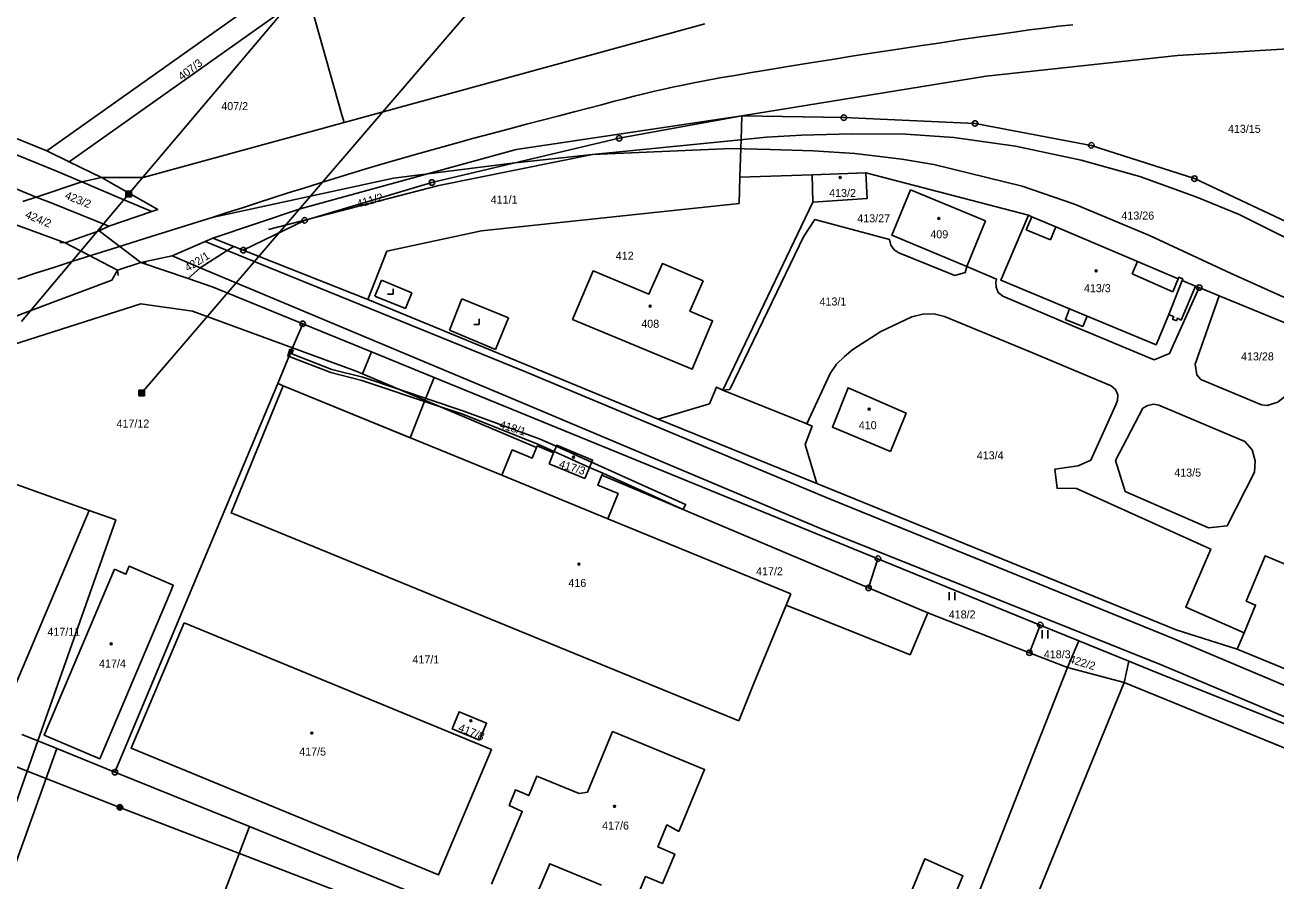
# Model space of a CAD drawing. Extents: x -587171 to -555306, y -1167727 to -1074732.
# Drawn here: x -560606.6 to -560378.5, y -1078590.7 to -1078434.4 of the extents above; entities that cross this region are included whole.
import ezdxf

# ---------------------------------------------------------------- set-up
doc = ezdxf.new("R2010")
doc.units = 0
for name, color, linetype in [('Hranice parcel', 7, 'Continuous'), ('Parcelní čísla', 7, 'Continuous'), ('Poz předměty', 7, 'Continuous'), ('Vnitřní kresba', 7, 'Continuous'), ('Věcná břemena k části', 7, 'Continuous'), ('Značky bodu BP', 7, 'Continuous'), ('Značky budov', 7, 'Continuous'), ('Značky kultur', 7, 'Continuous')]:
    doc.layers.add(name, color=color, linetype=linetype)

msp = doc.modelspace()

# ---------------------------------------------------------------- linework, layer by layer
at = {"layer": 'Hranice parcel'}
for p, q in [((-560602.65, -1078457.42), (-560556.22, -1078424.49)), ((-560555.07, -1078428.57), (-560598.55, -1078459.41)), ((-560342.84, -1078436.82), (-560396.43, -1078439.99)), ((-560640.02, -1078442.1), (-560602.65, -1078457.42)), ((-560640.44, -1078451.19), (-560604.57, -1078465.85)), ((-560585.07, -1078462.27), (-560548.39, -1078452.22)), ((-560602.65, -1078457.42), (-560598.55, -1078459.41)), ((-560598.55, -1078459.41), (-560592.63, -1078462.29)), ((-560592.63, -1078462.29), (-560585.07, -1078462.27)), ((-560463.06, -1078461.81), (-560476.23, -1078462.2)), ((-560453.25, -1078461.44), (-560463.06, -1078461.81)), ((-560462.92, -1078466.77), (-560463.06, -1078461.81)), ((-560453.25, -1078461.44), (-560423.57, -1078469.17)), ((-560604.57, -1078465.85), (-560606.99, -1078466.66)), ((-560604.57, -1078465.85), (-560601.84, -1078466.88)), ((-560601.84, -1078466.88), (-560591.3, -1078471.17)), ((-560479.35, -1078501.1), (-560462.92, -1078466.77)), ((-560572.37, -1078473.32), (-560568.53, -1078474.84)), ((-560568.53, -1078474.84), (-560566.79, -1078475.53)), ((-560566.79, -1078475.53), (-560544.07, -1078484.52)), ((-560585.48, -1078477.81), (-560576.86, -1078480.73)), ((-560393.13, -1078482.08), (-560392.45, -1078482.36)), ((-560388.8, -1078483.87), (-560392.45, -1078482.36)), ((-560544.07, -1078484.52), (-560491.12, -1078506.35)), ((-560388.8, -1078483.87), (-560371.78, -1078490.9)), ((-560555.96, -1078488.96), (-560557.8, -1078493.38)), ((-560557.8, -1078493.38), (-560546.21, -1078497.63)), ((-560546.21, -1078497.63), (-560513.3, -1078511.55)), ((-560451.04, -1078531.84), (-560532.01, -1078498.75)), ((-560519.65, -1078516.62), (-560559.52, -1078500.28)), ((-560491.12, -1078506.35), (-560462.21, -1078518.1)), ((-560500.32, -1078524.54), (-560519.65, -1078516.62)), ((-560452.76, -1078537.17), (-560501.4, -1078516.58)), ((-560611.42, -1078562.04), (-560594.92, -1078523.02)), ((-560466.92, -1078538.23), (-560500.32, -1078524.54)), ((-560452.76, -1078537.17), (-560451.04, -1078531.84)), ((-560421.44, -1078543.94), (-560451.04, -1078531.84)), ((-560441.97, -1078541.72), (-560452.76, -1078537.17)), ((-560467.8, -1078540.32), (-560466.92, -1078538.23)), ((-560441.97, -1078541.72), (-560423.42, -1078549)), ((-560423.42, -1078549), (-560421.44, -1078543.94)), ((-560414.4, -1078546.81), (-560421.44, -1078543.94)), ((-560416.49, -1078551.7), (-560414.4, -1078546.81)), ((-560405.27, -1078550.54), (-560414.4, -1078546.81)), ((-560385.52, -1078548.35), (-560384.25, -1078545.35)), ((-560423.42, -1078549), (-560416.49, -1078551.7)), ((-560385.52, -1078548.35), (-560330.86, -1078570.95)), ((-560446.84, -1078628.92), (-560416.49, -1078551.7)), ((-560406.12, -1078554.4), (-560416.49, -1078551.7)), ((-560406.12, -1078554.4), (-560405.27, -1078550.54)), ((-560318.62, -1078590.37), (-560406.12, -1078554.4)), ((-560604.25, -1078565.1), (-560609.07, -1078578.79)), ((-560604.25, -1078565.1), (-560607.16, -1078563.92)), ((-560600.81, -1078566.5), (-560604.25, -1078565.1)), ((-560638.59, -1078671.27), (-560600.81, -1078566.5)), ((-560590.21, -1078570.8), (-560600.81, -1078566.5)), ((-560590.21, -1078570.8), (-560565.69, -1078580.73)), ((-560604.5, -1078683.21), (-560565.69, -1078580.73)), ((-560565.69, -1078580.73), (-560446.84, -1078628.92))]:
    msp.add_line(p, q, dxfattribs=at)
for points in [[(-560555.07, -1078428.57), (-560548.79, -1078450.81), (-560548.39, -1078452.22)], [(-560548.39, -1078452.22), (-560484.63, -1078434.75), (-560482.64, -1078434.21)], [(-560396.43, -1078439.99), (-560431.28, -1078443.77), (-560475.85, -1078451.01)], [(-560475.85, -1078451.01), (-560517.03, -1078457.13), (-560556.44, -1078467.98), (-560572.37, -1078473.32)], [(-560475.85, -1078451.01), (-560498.24, -1078455.12), (-560532.39, -1078463.18), (-560555.6, -1078470.09), (-560566.79, -1078475.53)], [(-560476.23, -1078462.2), (-560476.05, -1078456.93), (-560476, -1078455.37), (-560475.85, -1078451.01)], [(-560475.85, -1078451.01), (-560457.27, -1078451.34), (-560433.34, -1078452.41), (-560412.13, -1078456.41), (-560393.32, -1078462.47), (-560368.14, -1078474.31), (-560366.28, -1078475.31)], [(-560592.63, -1078462.29), (-560596.23, -1078463.07), (-560604.57, -1078465.85)], [(-560592.63, -1078462.29), (-560582.38, -1078468.1), (-560583.46, -1078468.47), (-560591.3, -1078471.17)], [(-560544.07, -1078484.52), (-560540.61, -1078475.71), (-560523.37, -1078471.98), (-560476.37, -1078466.99), (-560476.23, -1078462.2)], [(-560462.92, -1078466.77), (-560453.04, -1078466.12), (-560453.25, -1078461.44)], [(-560431.45, -1078470.2), (-560445.1, -1078464.55), (-560448.53, -1078472.8), (-560434.85, -1078478.5), (-560431.45, -1078470.2)], [(-560591.3, -1078471.17), (-560593.05, -1078472.03), (-560599.28, -1078474.2), (-560613.44, -1078469.05)], [(-560423.57, -1078469.17), (-560428.66, -1078481), (-560416.09, -1078486.26), (-560416.86, -1078488.16), (-560413.65, -1078489.46), (-560412.87, -1078487.59), (-560400.33, -1078492.82), (-560398.02, -1078487.25), (-560397.11, -1078487.67), (-560397.3, -1078488.14), (-560396.62, -1078488.42), (-560396.43, -1078487.96), (-560395.77, -1078488.29), (-560393.13, -1078482.08)], [(-560393.13, -1078482.08), (-560395.57, -1078481.06), (-560395.46, -1078480.79), (-560396.15, -1078480.48), (-560396.27, -1078480.76), (-560403.72, -1078477.6), (-560418.59, -1078471.29), (-560422.96, -1078469.43), (-560423.57, -1078469.17)], [(-560392.45, -1078482.36), (-560397.87, -1078494.41), (-560400.64, -1078495.56), (-560415.67, -1078489.25), (-560428.26, -1078483.92), (-560429.11, -1078483.28), (-560429.48, -1078482.31), (-560429.55, -1078481.29), (-560429.44, -1078480.82), (-560434.85, -1078478.5), (-560435.12, -1078479.61), (-560437.02, -1078480.17), (-560447.22, -1078476), (-560448.11, -1078475.47), (-560448.71, -1078474.62), (-560448.96, -1078473.56), (-560462.55, -1078469.92), (-560464.62, -1078473.11), (-560471.14, -1078486.59), (-560478.07, -1078500.96), (-560479.35, -1078501.1)], [(-560585.48, -1078477.81), (-560579.74, -1078476.59), (-560573.74, -1078473.93), (-560572.37, -1078473.32)], [(-560576.86, -1078480.73), (-560574.63, -1078478.74), (-560569.71, -1078475.57), (-560568.53, -1078474.84)], [(-560647.85, -1078502.5), (-560647.06, -1078502.19), (-560644.13, -1078501.04), (-560642.96, -1078500.58), (-560590.78, -1078481.03), (-560589.74, -1078479.18), (-560585.48, -1078477.81)], [(-560482.94, -1078481.1), (-560490.33, -1078477.94), (-560492.81, -1078483.57), (-560502.99, -1078479.31), (-560506.74, -1078488.18), (-560484.92, -1078497.27), (-560481.21, -1078488.42), (-560485.36, -1078486.69), (-560482.94, -1078481.1)], [(-560576.86, -1078480.73), (-560572.28, -1078482.29), (-560555.96, -1078488.96)], [(-560371.78, -1078490.9), (-560372, -1078491.42), (-560376.52, -1078501.99), (-560378.14, -1078503.3), (-560380.08, -1078503.89), (-560381.11, -1078503.77), (-560392.16, -1078499.12), (-560392.91, -1078498.3), (-560393.21, -1078496.31), (-560388.8, -1078483.87)], [(-560462.21, -1078518.1), (-560464.32, -1078511.01), (-560463.05, -1078507.64), (-560464.03, -1078507.25), (-560459.73, -1078498.03), (-560458.59, -1078496.34), (-560457.16, -1078494.91), (-560455.6, -1078493.68), (-560450.54, -1078490.4), (-560444.84, -1078487.71), (-560442.88, -1078487.19), (-560440.87, -1078487.16), (-560438.91, -1078487.63), (-560423.27, -1078494.09), (-560408.51, -1078500.26), (-560407.72, -1078500.93), (-560407.31, -1078501.91), (-560407.38, -1078502.95), (-560407.73, -1078503.88), (-560412.25, -1078513.87), (-560414.51, -1078514.91), (-560418.78, -1078515.47), (-560418.39, -1078518.97), (-560414.85, -1078519.03), (-560390.35, -1078530.07), (-560394.91, -1078540.67), (-560384.25, -1078545.35)], [(-560532.01, -1078498.75), (-560543.43, -1078494.08), (-560555.96, -1078488.96)], [(-560557.8, -1078493.38), (-560560.52, -1078499.87), (-560590.21, -1078570.8)], [(-560559.52, -1078500.28), (-560569.02, -1078523.47), (-560476.43, -1078561.42), (-560473.6, -1078554.44), (-560467.8, -1078540.32)], [(-560491.12, -1078506.35), (-560481.78, -1078503.55), (-560480.46, -1078500.52), (-560479.35, -1078501.1)], [(-560448.75, -1078512.25), (-560445.9, -1078505.26), (-560456.49, -1078500.64), (-560459.36, -1078507.83), (-560448.75, -1078512.25)], [(-560594.92, -1078523.02), (-560646.27, -1078504.66), (-560647.85, -1078502.5)], [(-560401.84, -1078503.88), (-560400.82, -1078503.66), (-560399.79, -1078503.83), (-560384.11, -1078510.42), (-560382.8, -1078511.97), (-560382.25, -1078513.95), (-560382.39, -1078516.02), (-560387.36, -1078525.83), (-560390.76, -1078526.19), (-560405.93, -1078519.55), (-560407.7, -1078513.91), (-560402.76, -1078504.38), (-560401.84, -1078503.88)], [(-560513.3, -1078511.55), (-560514.09, -1078513.49), (-560517.75, -1078511.99), (-560519.65, -1078516.62)], [(-560501.4, -1078516.58), (-560501.25, -1078516.21), (-560503.65, -1078515.18), (-560503.1, -1078513.83), (-560509.63, -1078511.1), (-560510.2, -1078512.49), (-560513.18, -1078511.27), (-560513.3, -1078511.55)], [(-560501.4, -1078516.58), (-560502.14, -1078518.39), (-560498.43, -1078519.91), (-560500.32, -1078524.54)], [(-560462.21, -1078518.1), (-560396.63, -1078544.83), (-560385.52, -1078548.35)], [(-560604.25, -1078565.1), (-560590.04, -1078524.77), (-560594.92, -1078523.02)], [(-560590.29, -1078533.76), (-560603.1, -1078564.05), (-560592.94, -1078568.36), (-560580.14, -1078538.09), (-560579.57, -1078536.68), (-560587.61, -1078533.21), (-560588.2, -1078534.66), (-560590.29, -1078533.76)], [(-560384.25, -1078545.35), (-560382.16, -1078540.3), (-560383.89, -1078539.58), (-560380.43, -1078531.33), (-560334.47, -1078550.54), (-560333.75, -1078548.7), (-560323.26, -1078553.08)], [(-560467.8, -1078540.32), (-560445.17, -1078549.38), (-560441.97, -1078541.72)], [(-560577.57, -1078543.55), (-560587.27, -1078566.4), (-560531.18, -1078589.54), (-560521.55, -1078566.64), (-560577.57, -1078543.55)], [(-560316.88, -1078586.02), (-560401.3, -1078552.16), (-560405.27, -1078550.54)], [(-560479.26, -1078737.71), (-560448.7, -1078658.64), (-560406.12, -1078554.4)], [(-560523.69, -1078564.97), (-560522.41, -1078561.87), (-560527.44, -1078559.78), (-560528.68, -1078562.88), (-560523.69, -1078564.97)], [(-560495.37, -1078594.54), (-560493.42, -1078589.85), (-560490.36, -1078591.12), (-560488.1, -1078585.73), (-560491.16, -1078584.45), (-560489.65, -1078580.7), (-560489.54, -1078580.42), (-560487.36, -1078581.61), (-560482.65, -1078570.29), (-560499.44, -1078563.4), (-560503.99, -1078574.45), (-560505.53, -1078574.66), (-560513.26, -1078571.53), (-560514.73, -1078575.06), (-560517.13, -1078574.04), (-560518.29, -1078576.87), (-560515.91, -1078577.95), (-560521.5, -1078591.26)], [(-560513.8, -1078594.36), (-560510.89, -1078587.51), (-560501.49, -1078591.43)], [(-560449.67, -1078604.08), (-560442.75, -1078607.01), (-560435.57, -1078589.71), (-560442.48, -1078586.61), (-560449.67, -1078604.08)]]:
    msp.add_lwpolyline(points, dxfattribs=at)
at = {"layer": 'Poz předměty'}
for p, q in [((-560585.33, -1078501.61), (-560397.04, -1078281.84)), ((-560550.41, -1078421.15), (-560587.7, -1078465.29)), ((-560503.09, -1078458.08), (-560477.92, -1078455.56)), ((-560471.37, -1078454.91), (-560477.92, -1078455.56)), ((-560471.37, -1078454.91), (-560465, -1078454.54)), ((-560465, -1078454.54), (-560455.88, -1078454.33)), ((-560455.88, -1078454.33), (-560445.95, -1078454.39)), ((-560445.95, -1078454.39), (-560437.18, -1078454.98)), ((-560437.18, -1078454.98), (-560425.95, -1078456.56)), ((-560531.12, -1078463.72), (-560503.09, -1078458.08)), ((-560503.09, -1078458.08), (-560517.75, -1078459.65)), ((-560503.09, -1078458.08), (-560477.78, -1078457)), ((-560477.78, -1078457), (-560470.71, -1078457.16)), ((-560462.87, -1078457.4), (-560470.71, -1078457.16)), ((-560455.26, -1078457.89), (-560462.87, -1078457.4)), ((-560446.71, -1078458.91), (-560455.26, -1078457.89)), ((-560425.95, -1078456.56), (-560413.98, -1078459.08)), ((-560517.75, -1078459.65), (-560539.39, -1078462.41)), ((-560440.85, -1078459.91), (-560446.71, -1078458.91)), ((-560424.77, -1078463.84), (-560440.85, -1078459.91)), ((-560413.98, -1078459.08), (-560403.26, -1078462.1)), ((-560539.39, -1078462.41), (-560572.46, -1078469.57)), ((-560403.26, -1078462.1), (-560392.88, -1078465.88)), ((-560588.2, -1078464.79), (-560587.2, -1078464.79)), ((-560588.2, -1078465.79), (-560588.2, -1078464.79)), ((-560588.2, -1078464.99), (-560587.2, -1078464.99)), ((-560588, -1078465.79), (-560588, -1078464.79)), ((-560587.8, -1078465.79), (-560587.8, -1078464.79)), ((-560587.6, -1078465.79), (-560587.6, -1078464.79)), ((-560587.4, -1078465.79), (-560587.4, -1078464.79)), ((-560587.2, -1078465.79), (-560587.2, -1078464.79)), ((-560562.18, -1078471.76), (-560531.12, -1078463.72)), ((-560415.21, -1078467.13), (-560424.77, -1078463.84)), ((-560607.25, -1078488.57), (-560587.7, -1078465.29)), ((-560588.2, -1078465.19), (-560587.2, -1078465.19)), ((-560588.2, -1078465.39), (-560587.2, -1078465.39)), ((-560588.2, -1078465.59), (-560587.2, -1078465.59)), ((-560588.2, -1078465.79), (-560587.2, -1078465.79)), ((-560401.55, -1078472.83), (-560415.21, -1078467.13)), ((-560392.88, -1078465.88), (-560385.18, -1078469)), ((-560385.18, -1078469), (-560371.15, -1078476.07)), ((-560386.6, -1078479.78), (-560401.55, -1078472.83)), ((-560377.02, -1078484.08), (-560386.6, -1078479.78)), ((-560585.83, -1078501.11), (-560584.83, -1078501.11)), ((-560585.83, -1078502.11), (-560585.83, -1078501.11)), ((-560585.83, -1078501.31), (-560584.83, -1078501.31)), ((-560585.83, -1078501.51), (-560584.83, -1078501.51)), ((-560585.63, -1078502.11), (-560585.63, -1078501.11)), ((-560585.43, -1078502.11), (-560585.43, -1078501.11)), ((-560585.23, -1078502.11), (-560585.23, -1078501.11)), ((-560585.03, -1078502.11), (-560585.03, -1078501.11)), ((-560584.83, -1078502.11), (-560584.83, -1078501.11)), ((-560585.83, -1078501.71), (-560584.83, -1078501.71)), ((-560585.83, -1078501.91), (-560584.83, -1078501.91)), ((-560585.83, -1078502.11), (-560584.83, -1078502.11)), ((-560659.22, -1078549.88), (-560589.29, -1078577.22)), ((-560589.29, -1078577.22), (-560519.5, -1078604.06))]:
    msp.add_line(p, q, dxfattribs=at)
for points in [[(-560415.52, -1078434.38), (-560418.09, -1078434.67), (-560420.72, -1078435), (-560423.4, -1078435.34), (-560426.21, -1078435.73), (-560429.23, -1078436.15), (-560432.43, -1078436.61), (-560435.88, -1078437.11), (-560439.58, -1078437.67), (-560443.41, -1078438.24), (-560447.35, -1078438.84), (-560451.41, -1078439.47), (-560455.43, -1078440.09), (-560459.41, -1078440.72), (-560463.36, -1078441.35), (-560467.13, -1078441.95), (-560470.71, -1078442.54), (-560474.1, -1078443.11), (-560477.16, -1078443.63), (-560479.91, -1078444.11), (-560482.39, -1078444.57), (-560484.61, -1078444.99), (-560486.63, -1078445.39), (-560488.53, -1078445.79), (-560490.31, -1078446.18), (-560492.03, -1078446.58), (-560493.76, -1078447), (-560495.51, -1078447.44), (-560497.35, -1078447.91), (-560499.34, -1078448.43), (-560501.49, -1078448.99), (-560503.85, -1078449.6), (-560506.45, -1078450.28), (-560509.19, -1078451), (-560512.07, -1078451.75), (-560515.13, -1078452.56), (-560518.24, -1078453.38), (-560521.44, -1078454.24), (-560524.72, -1078455.12), (-560527.99, -1078456.01), (-560531.27, -1078456.92), (-560534.56, -1078457.84), (-560537.76, -1078458.75), (-560540.9, -1078459.66), (-560544, -1078460.58), (-560547.01, -1078461.48), (-560549.96, -1078462.38), (-560552.9, -1078463.29), (-560555.77, -1078464.19), (-560558.59, -1078465.09), (-560561.42, -1078465.99), (-560564.2, -1078466.88), (-560566.95, -1078467.78), (-560569.72, -1078468.68), (-560572.46, -1078469.57)], [(-560607.92, -1078480.8), (-560604.69, -1078479.75), (-560601.36, -1078478.67), (-560597.9, -1078477.56), (-560594.42, -1078476.46), (-560590.87, -1078475.33), (-560587.22, -1078474.19), (-560583.58, -1078473.04), (-560579.91, -1078471.89), (-560576.17, -1078470.73), (-560572.46, -1078469.57)]]:
    msp.add_lwpolyline(points, dxfattribs=at)
for radius in [0.5, 0.4, 0.3, 0.2, 0.1]:
    msp.add_circle((-560589.29, -1078577.22), radius, dxfattribs=at)
at = {"layer": 'Vnitřní kresba'}
for p, q in [((-560637.85, -1078445.99), (-560601, -1078461.05)), ((-560601, -1078461.05), (-560596.23, -1078463.07)), ((-560596.23, -1078463.07), (-560588.26, -1078466.44)), ((-560588.26, -1078466.44), (-560583.46, -1078468.47)), ((-560422.96, -1078469.43), (-560423.99, -1078471.85)), ((-560592.63, -1078471.12), (-560593.05, -1078472.03)), ((-560423.99, -1078471.85), (-560419.59, -1078473.65)), ((-560419.59, -1078473.65), (-560418.59, -1078471.29)), ((-560600.28, -1078474.15), (-560599.28, -1078474.2)), ((-560593.05, -1078472.03), (-560585.48, -1078477.81)), ((-560573.74, -1078473.93), (-560569.71, -1078475.57)), ((-560589.74, -1078479.18), (-560599.28, -1078474.2)), ((-560569.71, -1078475.57), (-560515.74, -1078497.56)), ((-560584.48, -1078477.79), (-560585.48, -1078477.81)), ((-560574.63, -1078478.74), (-560579.74, -1078476.59)), ((-560518.36, -1078502.38), (-560574.63, -1078478.74)), ((-560403.72, -1078477.6), (-560404.69, -1078479.88)), ((-560589.62, -1078480.17), (-560589.74, -1078479.18)), ((-560542.79, -1078483.95), (-560541.59, -1078480.99)), ((-560541.59, -1078480.99), (-560536.07, -1078483.31)), ((-560404.69, -1078479.88), (-560397.28, -1078483.15)), ((-560397.28, -1078483.15), (-560396.27, -1078480.76)), ((-560536.07, -1078483.31), (-560537.2, -1078486.16)), ((-560398.02, -1078487.25), (-560395.57, -1078481.06)), ((-560643.31, -1078503.79), (-560585.49, -1078485.35)), ((-560585.49, -1078485.35), (-560576.08, -1078486.67)), ((-560537.2, -1078486.16), (-560542.79, -1078483.95)), ((-560529.19, -1078490.14), (-560526.93, -1078484.44)), ((-560526.93, -1078484.44), (-560518.43, -1078487.91)), ((-560576.08, -1078486.67), (-560557.8, -1078493.38)), ((-560416.09, -1078486.26), (-560412.87, -1078487.59)), ((-560520.8, -1078493.64), (-560529.19, -1078490.14)), ((-560518.43, -1078487.91), (-560520.8, -1078493.64)), ((-560515.74, -1078497.56), (-560459.88, -1078520.93)), ((-560479.35, -1078501.1), (-560464.03, -1078507.25)), ((-560461.53, -1078526.3), (-560518.36, -1078502.38)), ((-560510.2, -1078512.49), (-560511.03, -1078514.53)), ((-560511.03, -1078514.53), (-560504.49, -1078517.21)), ((-560504.49, -1078517.21), (-560503.65, -1078515.18)), ((-560459.88, -1078520.93), (-560396.93, -1078546.54)), ((-560399.09, -1078551.32), (-560461.53, -1078526.3)), ((-560396.93, -1078546.54), (-560315.03, -1078581.04)), ((-560399.09, -1078551.32), (-560316.88, -1078586.02))]:
    msp.add_line(p, q, dxfattribs=at)
at = {"layer": 'Věcná břemena k části'}
for points in [[(-560560.52, -1078499.87), (-560559.52, -1078500.28), (-560536.36, -1078509.77), (-560533.67, -1078502.94), (-560532.01, -1078498.75), (-560543.43, -1078494.08), (-560545.05, -1078498.12), (-560546.21, -1078497.63), (-560557.8, -1078493.38)], [(-560558.29, -1078493.58), (-560558.67, -1078494.84), (-560558.45, -1078494.93), (-560557.93, -1078493.69)], [(-560538.46, -1078500.91), (-560544.98, -1078498.72), (-560550.66, -1078497.28), (-560557.93, -1078494.48), (-560557.72, -1078493.75), (-560557.93, -1078493.69), (-560558.45, -1078494.93), (-560550.84, -1078497.86), (-560545.16, -1078499.3), (-560531.2, -1078503.98), (-560526.96, -1078505.4), (-560513.05, -1078510.94), (-560510.11, -1078512.27), (-560503.65, -1078515.18), (-560501.25, -1078516.21), (-560486.54, -1078522.84), (-560486.13, -1078521.93), (-560503.26, -1078514.23), (-560509.73, -1078511.33), (-560512.65, -1078510.02), (-560526.74, -1078504.84)]]:
    msp.add_lwpolyline(points, close=True, dxfattribs=at)
at = {"layer": 'Značky bodu BP'}
for centre, radius in [((-560457.27, -1078451.34), 0.5), ((-560457.27, -1078451.34), 0.0303), ((-560433.34, -1078452.41), 0.5), ((-560433.34, -1078452.41), 0.0303), ((-560498.24, -1078455.12), 0.5), ((-560498.24, -1078455.12), 0.0303), ((-560412.13, -1078456.41), 0.5), ((-560412.13, -1078456.41), 0.0303), ((-560532.39, -1078463.18), 0.5), ((-560393.32, -1078462.47), 0.5), ((-560393.32, -1078462.47), 0.0303), ((-560532.39, -1078463.18), 0.0303), ((-560555.6, -1078470.09), 0.5), ((-560555.6, -1078470.09), 0.0303), ((-560566.79, -1078475.53), 0.5), ((-560566.79, -1078475.53), 0.0303), ((-560392.45, -1078482.36), 0.5), ((-560392.45, -1078482.36), 0.0303), ((-560555.96, -1078488.96), 0.5), ((-560555.96, -1078488.96), 0.0303), ((-560451.04, -1078531.84), 0.5), ((-560451.04, -1078531.84), 0.0303), ((-560452.76, -1078537.17), 0.5), ((-560452.76, -1078537.17), 0.0303), ((-560421.44, -1078543.94), 0.5), ((-560421.44, -1078543.94), 0.0303), ((-560423.42, -1078549), 0.5), ((-560423.42, -1078549), 0.0303), ((-560590.21, -1078570.8), 0.5), ((-560590.21, -1078570.8), 0.0303)]:
    msp.add_circle(centre, radius, dxfattribs=at)
at = {"layer": 'Značky budov'}
for centre in [(-560457.92, -1078462.25), (-560439.95, -1078469.74), (-560411.26, -1078479.3), (-560492.6, -1078485.74), (-560452.64, -1078504.54), (-560506.56, -1078513.31), (-560505.57, -1078532.82), (-560590.88, -1078547.39), (-560525.28, -1078561.4), (-560554.3, -1078563.65), (-560499.08, -1078577.03)]:
    msp.add_circle(centre, 0.175, dxfattribs=at)
at = {"layer": 'Značky kultur'}
for p, q in [((-560539.47, -1078483.56), (-560539.47, -1078482.56)), ((-560540.47, -1078483.56), (-560539.47, -1078483.56)), ((-560524.76, -1078489.09), (-560523.76, -1078489.09)), ((-560523.76, -1078489.09), (-560523.76, -1078488.09)), ((-560438.04, -1078539.43), (-560438.04, -1078537.93)), ((-560437.04, -1078539.43), (-560437.04, -1078537.93)), ((-560421.07, -1078546.38), (-560421.07, -1078544.88)), ((-560420.07, -1078546.38), (-560420.07, -1078544.88))]:
    msp.add_line(p, q, dxfattribs=at)

# ---------------------------------------------------------------- texts
at = {"layer": 'Parcelní čísla'}
for s, rotation, p in [('407/3', 37, (-560577.99, -1078444.6)), ('423/2', 338, (-560599.45, -1078466.07)), ('411/2', 16, (-560545.85, -1078467.83)), ('424/2', 337, (-560606.7, -1078469.55)), ('422/1', 32, (-560576.92, -1078479.53)), ('418/1', 343, (-560520.2, -1078507.97)), ('417/3', 343, (-560509.35, -1078515.16)), ('422/2', 343, (-560416.33, -1078550.77)), ('417/8', 338, (-560527.7, -1078563.22))]:
    msp.add_text(s, height=1.46, rotation=rotation, dxfattribs=at).set_placement(p)
for s, p in [('407/2', (-560570.8, -1078449.97)), ('413/15', (-560387.21, -1078454.12)), ('413/2', (-560459.94, -1078465.82)), ('411/1', (-560521.67, -1078467.03)), ('413/27', (-560454.81, -1078470.45)), ('413/26', (-560406.64, -1078469.95)), ('409', (-560441.49, -1078473.36)), ('412', (-560498.86, -1078477.27)), ('413/3', (-560413.48, -1078483.2)), ('413/1', (-560461.7, -1078485.63)), ('408', (-560494.2, -1078489.69)), ('413/28', (-560384.82, -1078495.65)), ('417/12', (-560589.91, -1078507.9)), ('410', (-560454.54, -1078508.21)), ('413/4', (-560433.02, -1078513.7)), ('413/5', (-560397, -1078516.85)), ('417/2', (-560473.27, -1078534.86)), ('416', (-560507.5, -1078536.99)), ('418/2', (-560438.13, -1078542.74)), ('417/11', (-560602.51, -1078545.89)), ('417/1', (-560535.93, -1078550.95)), ('418/3', (-560420.79, -1078550.01)), ('417/4', (-560593.09, -1078551.7)), ('417/5', (-560556.59, -1078567.77)), ('417/6', (-560501.35, -1078581.27))]:
    msp.add_text(s, height=1.46, dxfattribs=at).set_placement(p)

doc.saveas('drawing.dxf')
